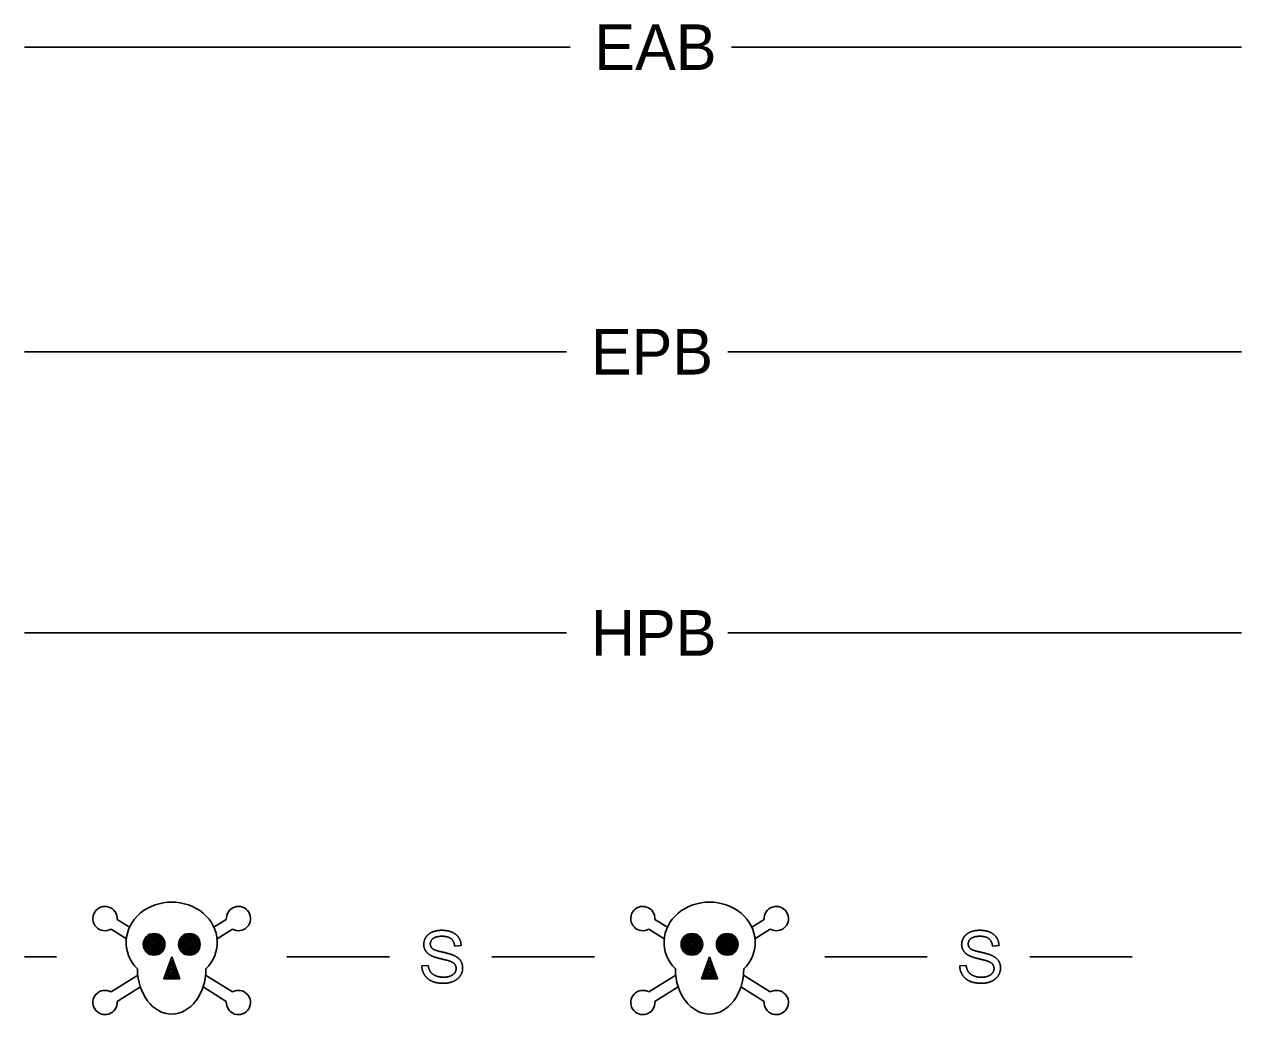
# Model space of a CAD drawing. Extents: x 0 to 3, y 0 to 1.83.
# Drawn here: x 0.5326 to 0.6672, y 1.0098 to 1.1192 of the extents above; entities that cross this region are included whole.
import ezdxf

# ---------------------------------------------------------------- set-up
doc = ezdxf.new("R2010")
doc.units = 0
doc.layers.add('Sheet_Symbology', color=7, linetype='Continuous')

msp = doc.modelspace()

# ---------------------------------------------------------------- linework, layer by layer
at = {"layer": 'Sheet_Symbology'}
for p, q in [((0.5326312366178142, 1.116638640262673), (0.5929363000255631, 1.116638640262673)), ((0.6107608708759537, 1.116638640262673), (0.6671562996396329, 1.116638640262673)), ((0.5326312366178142, 1.0830073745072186), (0.5925579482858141, 1.0830073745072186)), ((0.6103825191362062, 1.0830073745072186), (0.6671562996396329, 1.0830073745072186)), ((0.5326312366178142, 1.0519434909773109), (0.5925579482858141, 1.0519434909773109)), ((0.6103825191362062, 1.0519434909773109), (0.6671562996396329, 1.0519434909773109)), ((0.5428799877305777, 1.0202964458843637), (0.5442527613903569, 1.019433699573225)), ((0.5549512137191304, 1.0202964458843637), (0.5535784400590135, 1.019433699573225)), ((0.6023232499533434, 1.0202964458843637), (0.6036960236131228, 1.019433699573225)), ((0.6143944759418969, 1.0202964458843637), (0.6130217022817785, 1.019433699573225)), ((0.5422086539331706, 1.0192282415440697), (0.5439043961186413, 1.0181625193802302)), ((0.5556225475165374, 1.0192282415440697), (0.5539268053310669, 1.018162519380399)), ((0.6016519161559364, 1.0192282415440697), (0.603347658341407, 1.0181625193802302)), ((0.6150658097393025, 1.0192282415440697), (0.6133700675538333, 1.018162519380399)), ((0.5809004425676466, 1.0174082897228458), (0.580184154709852, 1.0173521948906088)), ((0.6403437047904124, 1.0174082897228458), (0.6396274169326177, 1.0173521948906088)), ((0.5326312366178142, 1.0161698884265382), (0.5361777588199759, 1.0161698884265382)), ((0.5489156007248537, 1.0157581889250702), (0.5489156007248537, 1.0157581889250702)), ((0.5616534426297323, 1.0161698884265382), (0.572975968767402, 1.0161698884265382)), ((0.5842984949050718, 1.0161698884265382), (0.5956210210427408, 1.0161698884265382)), ((0.6083588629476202, 1.0157581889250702), (0.6083588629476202, 1.0157581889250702)), ((0.621096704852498, 1.0161698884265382), (0.6324192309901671, 1.0161698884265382)), ((0.6437417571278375, 1.0161698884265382), (0.6550642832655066, 1.0161698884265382)), ((0.5765595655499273, 1.0151601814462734), (0.5772672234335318, 1.0152205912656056)), ((0.6360028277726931, 1.0151601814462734), (0.6367104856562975, 1.0152205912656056)), ((0.5451690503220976, 1.0141486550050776), (0.5422086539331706, 1.0122881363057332)), ((0.5526621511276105, 1.0141486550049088), (0.5556225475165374, 1.0122881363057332)), ((0.6046123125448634, 1.0141486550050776), (0.6016519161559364, 1.0122881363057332)), ((0.612105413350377, 1.0141486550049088), (0.6150658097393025, 1.0122881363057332)), ((0.5454544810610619, 1.01283792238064), (0.5428799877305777, 1.0112199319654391)), ((0.5523767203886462, 1.0128379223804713), (0.5549512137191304, 1.0112199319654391)), ((0.6048977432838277, 1.01283792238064), (0.6023232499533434, 1.0112199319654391)), ((0.6118199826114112, 1.0128379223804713), (0.6143944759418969, 1.0112199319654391))]:
    msp.add_line(p, q, dxfattribs=at)
for points in [[(0.5489156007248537, 1.0161698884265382), (0.5480286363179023, 1.0137470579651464), (0.5498025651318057, 1.0137470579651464)], [(0.5489156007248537, 1.0157581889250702), (0.5482311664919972, 1.0138885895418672), (0.5496000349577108, 1.0138885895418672)], [(0.6083588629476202, 1.0161698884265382), (0.6074718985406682, 1.0137470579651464), (0.6092458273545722, 1.0137470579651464)], [(0.6083588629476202, 1.0157581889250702), (0.6076744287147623, 1.0138885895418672), (0.6090432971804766, 1.0138885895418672)], [(0.5489156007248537, 1.015346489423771), (0.5484336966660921, 1.014030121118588), (0.5493975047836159, 1.014030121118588)], [(0.5489156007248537, 1.014934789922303), (0.548636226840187, 1.0141716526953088), (0.5491949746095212, 1.0141716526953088)], [(0.5489156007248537, 1.0145230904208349), (0.5488387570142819, 1.0143131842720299), (0.5489924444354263, 1.0143131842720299)], [(0.6083588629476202, 1.015346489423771), (0.6078769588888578, 1.014030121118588), (0.6088407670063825, 1.014030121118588)], [(0.6083588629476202, 1.014934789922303), (0.608079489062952, 1.0141716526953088), (0.6086382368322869, 1.0141716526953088)], [(0.6083588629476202, 1.0145230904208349), (0.6082820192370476, 1.0143131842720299), (0.6084357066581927, 1.0143131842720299)]]:
    msp.add_lwpolyline(points, close=True, dxfattribs=at)
for centre, radius in [((0.5469651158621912, 1.0175476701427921), 0.0012001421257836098), ((0.5469651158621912, 1.0175476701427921), 0.0010586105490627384), ((0.5469651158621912, 1.0175476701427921), 0.0009170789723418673), ((0.5508660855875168, 1.0175476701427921), 0.0012001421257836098), ((0.5508660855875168, 1.0175476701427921), 0.0010586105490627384), ((0.5508660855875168, 1.0175476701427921), 0.0009170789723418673), ((0.6064083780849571, 1.0175476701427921), 0.0012001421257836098), ((0.6064083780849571, 1.0175476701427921), 0.0010586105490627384), ((0.6064083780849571, 1.0175476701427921), 0.0009170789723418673), ((0.6103093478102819, 1.0175476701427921), 0.0012001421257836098), ((0.6103093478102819, 1.0175476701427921), 0.0010586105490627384), ((0.6103093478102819, 1.0175476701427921), 0.0009170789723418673), ((0.5469651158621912, 1.0175476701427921), 0.0007755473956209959), ((0.5469651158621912, 1.0175476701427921), 0.0006340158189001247), ((0.5469651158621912, 1.0175476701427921), 0.0004924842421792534), ((0.5469651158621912, 1.0175476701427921), 0.00035095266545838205), ((0.5469651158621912, 1.0175476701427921), 0.00020942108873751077), ((0.5469651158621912, 1.0175476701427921), 6.788951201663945e-05), ((0.5508660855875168, 1.0175476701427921), 0.0007755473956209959), ((0.5508660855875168, 1.0175476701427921), 0.0006340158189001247), ((0.5508660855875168, 1.0175476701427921), 0.0004924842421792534), ((0.5508660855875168, 1.0175476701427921), 0.00035095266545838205), ((0.5508660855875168, 1.0175476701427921), 0.00020942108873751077), ((0.5508660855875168, 1.0175476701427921), 6.788951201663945e-05), ((0.6064083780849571, 1.0175476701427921), 0.0007755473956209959), ((0.6064083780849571, 1.0175476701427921), 0.0006340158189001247), ((0.6064083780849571, 1.0175476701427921), 0.0004924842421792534), ((0.6064083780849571, 1.0175476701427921), 0.00035095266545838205), ((0.6064083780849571, 1.0175476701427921), 0.00020942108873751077), ((0.6064083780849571, 1.0175476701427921), 6.788951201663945e-05), ((0.6103093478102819, 1.0175476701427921), 0.0007755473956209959), ((0.6103093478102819, 1.0175476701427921), 0.0006340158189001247), ((0.6103093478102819, 1.0175476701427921), 0.0004924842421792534), ((0.6103093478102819, 1.0175476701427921), 0.00035095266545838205), ((0.6103093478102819, 1.0175476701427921), 0.00020942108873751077), ((0.6103093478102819, 1.0175476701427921), 6.788951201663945e-05)]:
    msp.add_circle(centre, radius, dxfattribs=at)
for centre, start, end in [((0.5415417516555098, 1.0203924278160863), 355.8976156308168, 299.8061705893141), ((0.5562894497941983, 1.0203924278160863), 240.19382941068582, 184.10238436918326), ((0.6009850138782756, 1.0203924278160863), 355.8976156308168, 299.8061705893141), ((0.6157327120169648, 1.0203924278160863), 240.19382941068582, 184.10238436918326), ((0.5415417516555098, 1.0111239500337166), 60.19382941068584, 4.1023843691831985), ((0.5562894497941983, 1.0111239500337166), 175.89761563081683, 119.80617058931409), ((0.6009850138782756, 1.0111239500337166), 60.19382941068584, 4.1023843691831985), ((0.6157327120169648, 1.0111239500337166), 175.89761563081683, 119.80617058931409)]:
    msp.add_arc(centre, 0.0013416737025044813, start, end, dxfattribs=at)
for centre, major_axis, ratio, start_param, end_param in [((0.5489156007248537, 1.01775984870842), (0.005031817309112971, 0), 0.8850143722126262, 5.564242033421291, 10.143721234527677), ((0.6083588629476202, 1.01775984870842), (0.005031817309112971, 0), 0.8850143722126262, 5.564242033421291, 10.143721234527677), ((0.5489156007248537, 1.0148790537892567), (-8.091779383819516e-19, -0.005031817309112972), 0.752542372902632, 4.7227348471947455, 7.843635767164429), ((0.6083588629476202, 1.0148790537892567), (-8.091779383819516e-19, -0.005031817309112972), 0.752542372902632, 4.7227348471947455, 7.843635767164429)]:
    msp.add_ellipse(centre, major_axis=major_axis, ratio=ratio, start_param=start_param, end_param=end_param, dxfattribs=at)
for points in [[(0.5770148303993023, 1.0183403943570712), (0.5772586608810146, 1.0187133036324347), (0.577726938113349, 1.0189065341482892)], [(0.577726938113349, 1.0189065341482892), (0.5781952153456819, 1.019099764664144), (0.5787679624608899, 1.019099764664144)], [(0.578799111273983, 1.0184395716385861), (0.5781162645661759, 1.0184395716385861), (0.5778039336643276, 1.0181902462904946)], [(0.5787679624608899, 1.019099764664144), (0.5793988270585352, 1.019099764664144), (0.5798806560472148, 1.0188970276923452)], [(0.5797903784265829, 1.0181648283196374), (0.5794547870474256, 1.0184395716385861), (0.578799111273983, 1.0184395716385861)], [(0.5798806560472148, 1.0188970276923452), (0.5803624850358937, 1.0186942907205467), (0.5806217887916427, 1.0183003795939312)], [(0.6364580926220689, 1.0183403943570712), (0.6367019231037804, 1.0187133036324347), (0.6371702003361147, 1.0189065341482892)], [(0.6371702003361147, 1.0189065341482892), (0.6376384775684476, 1.019099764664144), (0.6382112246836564, 1.019099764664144)], [(0.638242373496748, 1.0184395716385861), (0.6375595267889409, 1.0184395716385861), (0.6372471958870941, 1.0181902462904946)], [(0.6382112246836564, 1.019099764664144), (0.6388420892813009, 1.019099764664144), (0.6393239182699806, 1.0188970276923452)], [(0.6392336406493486, 1.0181648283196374), (0.6388980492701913, 1.0184395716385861), (0.638242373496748, 1.0184395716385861)], [(0.6393239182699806, 1.0188970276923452), (0.6398057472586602, 1.0186942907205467), (0.6400650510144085, 1.0183003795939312)], [(0.5767709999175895, 1.0175385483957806), (0.5767709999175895, 1.0179674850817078), (0.5770148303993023, 1.0183403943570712)], [(0.5769699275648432, 1.0168332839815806), (0.5767709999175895, 1.0171482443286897), (0.5767709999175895, 1.0175385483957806)], [(0.5778039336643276, 1.0181902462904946), (0.5774916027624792, 1.0179409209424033), (0.5774916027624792, 1.0175891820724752)], [(0.5774916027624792, 1.0175891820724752), (0.5774916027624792, 1.0172838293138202), (0.5777127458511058, 1.0170866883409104)], [(0.5777127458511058, 1.0170866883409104), (0.5779300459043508, 1.0168895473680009), (0.5788475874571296, 1.016682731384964)], [(0.580184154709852, 1.0173521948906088), (0.5801259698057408, 1.0178900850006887), (0.5797903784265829, 1.0181648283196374)], [(0.5806217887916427, 1.0183003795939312), (0.5808810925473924, 1.0179064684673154), (0.5809004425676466, 1.0174082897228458)], [(0.6362142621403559, 1.0175385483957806), (0.6362142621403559, 1.0179674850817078), (0.6364580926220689, 1.0183403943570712)], [(0.6364131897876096, 1.0168332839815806), (0.6362142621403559, 1.0171482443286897), (0.6362142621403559, 1.0175385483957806)], [(0.6372471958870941, 1.0181902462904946), (0.6369348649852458, 1.0179409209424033), (0.6369348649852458, 1.0175891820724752)], [(0.6369348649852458, 1.0175891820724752), (0.6369348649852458, 1.0172838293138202), (0.6371560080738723, 1.0170866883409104)], [(0.6371560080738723, 1.0170866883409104), (0.6373733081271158, 1.0168895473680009), (0.6382908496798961, 1.016682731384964)], [(0.6396274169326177, 1.0173521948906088), (0.6395692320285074, 1.0178900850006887), (0.6392336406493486, 1.0181648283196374)], [(0.6400650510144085, 1.0183003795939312), (0.6403243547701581, 1.0179064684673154), (0.6403437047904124, 1.0174082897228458)], [(0.5775744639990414, 1.0163058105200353), (0.5771688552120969, 1.0165183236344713), (0.5769699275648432, 1.0168332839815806)], [(0.5786710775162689, 1.0159521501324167), (0.5778873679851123, 1.0161396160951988), (0.5775744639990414, 1.0163058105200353)], [(0.5796836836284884, 1.0156757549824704), (0.5794547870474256, 1.0157646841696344), (0.5786710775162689, 1.0159521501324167)], [(0.5788475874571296, 1.016682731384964), (0.5797651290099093, 1.016475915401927), (0.5801045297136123, 1.016321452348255)], [(0.5801943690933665, 1.0153415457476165), (0.5800406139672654, 1.0155405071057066), (0.5796836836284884, 1.0156757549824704)], [(0.5801045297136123, 1.016321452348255), (0.5805981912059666, 1.0160937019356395), (0.5808334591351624, 1.0157442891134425)], [(0.5808334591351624, 1.0157442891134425), (0.5810687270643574, 1.0153948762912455), (0.5810687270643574, 1.0149392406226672)], [(0.6370177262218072, 1.0163058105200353), (0.6366121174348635, 1.0165183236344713), (0.6364131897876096, 1.0168332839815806)], [(0.6381143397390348, 1.0159521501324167), (0.6373306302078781, 1.0161396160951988), (0.6370177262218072, 1.0163058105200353)], [(0.6391269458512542, 1.0156757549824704), (0.6388980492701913, 1.0157646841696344), (0.6381143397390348, 1.0159521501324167)], [(0.6382908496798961, 1.016682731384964), (0.639208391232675, 1.016475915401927), (0.639547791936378, 1.016321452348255)], [(0.6396376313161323, 1.0153415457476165), (0.6394838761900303, 1.0155405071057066), (0.6391269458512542, 1.0156757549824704)], [(0.639547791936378, 1.016321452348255), (0.6400414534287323, 1.0160937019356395), (0.6402767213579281, 1.0157442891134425)], [(0.6402767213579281, 1.0157442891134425), (0.6405119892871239, 1.0153948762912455), (0.6405119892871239, 1.0149392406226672)], [(0.5768706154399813, 1.0141423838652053), (0.5765750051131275, 1.0145923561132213), (0.5765595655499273, 1.0151601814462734)], [(0.5772672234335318, 1.0152205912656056), (0.5773174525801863, 1.01479509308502), (0.5775010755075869, 1.0145223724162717)], [(0.5775010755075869, 1.0145223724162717), (0.5776846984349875, 1.0142496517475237), (0.578071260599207, 1.0140814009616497)], [(0.5796986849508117, 1.014040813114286), (0.5800272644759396, 1.0141684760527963), (0.5801876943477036, 1.01439086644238)], [(0.5801876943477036, 1.01439086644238), (0.5803481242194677, 1.0146132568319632), (0.5803481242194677, 1.0148759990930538)], [(0.5803481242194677, 1.0148759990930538), (0.5803481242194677, 1.0151425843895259), (0.5801943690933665, 1.0153415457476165)], [(0.5810687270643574, 1.0149392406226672), (0.5810687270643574, 1.0144875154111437), (0.5808098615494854, 1.0140879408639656)], [(0.636313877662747, 1.0141423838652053), (0.6360182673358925, 1.0145923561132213), (0.6360028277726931, 1.0151601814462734)], [(0.6367104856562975, 1.0152205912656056), (0.636760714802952, 1.01479509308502), (0.6369443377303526, 1.0145223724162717)], [(0.6369443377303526, 1.0145223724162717), (0.6371279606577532, 1.0142496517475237), (0.6375145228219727, 1.0140814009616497)], [(0.6391419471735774, 1.014040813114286), (0.6394705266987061, 1.0141684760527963), (0.6396309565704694, 1.01439086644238)], [(0.6396309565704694, 1.01439086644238), (0.6397913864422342, 1.0146132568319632), (0.6397913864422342, 1.0148759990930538)], [(0.6397913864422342, 1.0148759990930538), (0.6397913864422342, 1.0151425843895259), (0.6396376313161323, 1.0153415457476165)], [(0.6405119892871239, 1.0149392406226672), (0.6405119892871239, 1.0144875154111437), (0.640253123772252, 1.0140879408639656)], [(0.5776859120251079, 1.0134683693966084), (0.5771662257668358, 1.0136924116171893), (0.5768706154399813, 1.0141423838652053)], [(0.5789744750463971, 1.0132443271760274), (0.57820559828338, 1.0132443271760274), (0.5776859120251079, 1.0134683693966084)], [(0.578071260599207, 1.0140814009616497), (0.5784578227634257, 1.0139131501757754), (0.5789410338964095, 1.0139131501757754)], [(0.5789410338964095, 1.0139131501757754), (0.5793701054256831, 1.0139131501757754), (0.5796986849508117, 1.014040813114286)], [(0.5800660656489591, 1.0134663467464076), (0.5795811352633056, 1.0132443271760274), (0.5789744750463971, 1.0132443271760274)], [(0.5808098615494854, 1.0140879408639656), (0.5805509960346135, 1.0136883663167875), (0.5800660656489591, 1.0134663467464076)], [(0.6371291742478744, 1.0134683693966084), (0.6366094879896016, 1.0136924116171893), (0.636313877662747, 1.0141423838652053)], [(0.6384177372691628, 1.0132443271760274), (0.6376488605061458, 1.0132443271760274), (0.6371291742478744, 1.0134683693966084)], [(0.6375145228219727, 1.0140814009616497), (0.6379010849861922, 1.0139131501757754), (0.6383842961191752, 1.0139131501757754)], [(0.6383842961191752, 1.0139131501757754), (0.6388133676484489, 1.0139131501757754), (0.6391419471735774, 1.014040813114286)], [(0.6395093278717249, 1.0134663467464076), (0.6390243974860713, 1.0132443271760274), (0.6384177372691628, 1.0132443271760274)], [(0.640253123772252, 1.0140879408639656), (0.6399942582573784, 1.0136883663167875), (0.6395093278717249, 1.0134663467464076)]]:
    msp.add_open_spline(points, degree=2, dxfattribs=at)

# ---------------------------------------------------------------- texts
for s, p in [('EAB', (0.5956268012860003, 1.114116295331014)), ('EPB', (0.5952484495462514, 1.0804850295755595)), ('HPB', (0.5952484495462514, 1.0494211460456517))]:
    msp.add_text(s, height=0.005044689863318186, dxfattribs=at).set_placement(p)

doc.saveas('drawing.dxf')
